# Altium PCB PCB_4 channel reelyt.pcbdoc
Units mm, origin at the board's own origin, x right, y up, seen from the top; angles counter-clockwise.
Board outline 128.64 x 103.34 mm, 2 copper layers (Top Layer, Bottom Layer); 44 components, 46 nets, 157 pads, 12 vias.
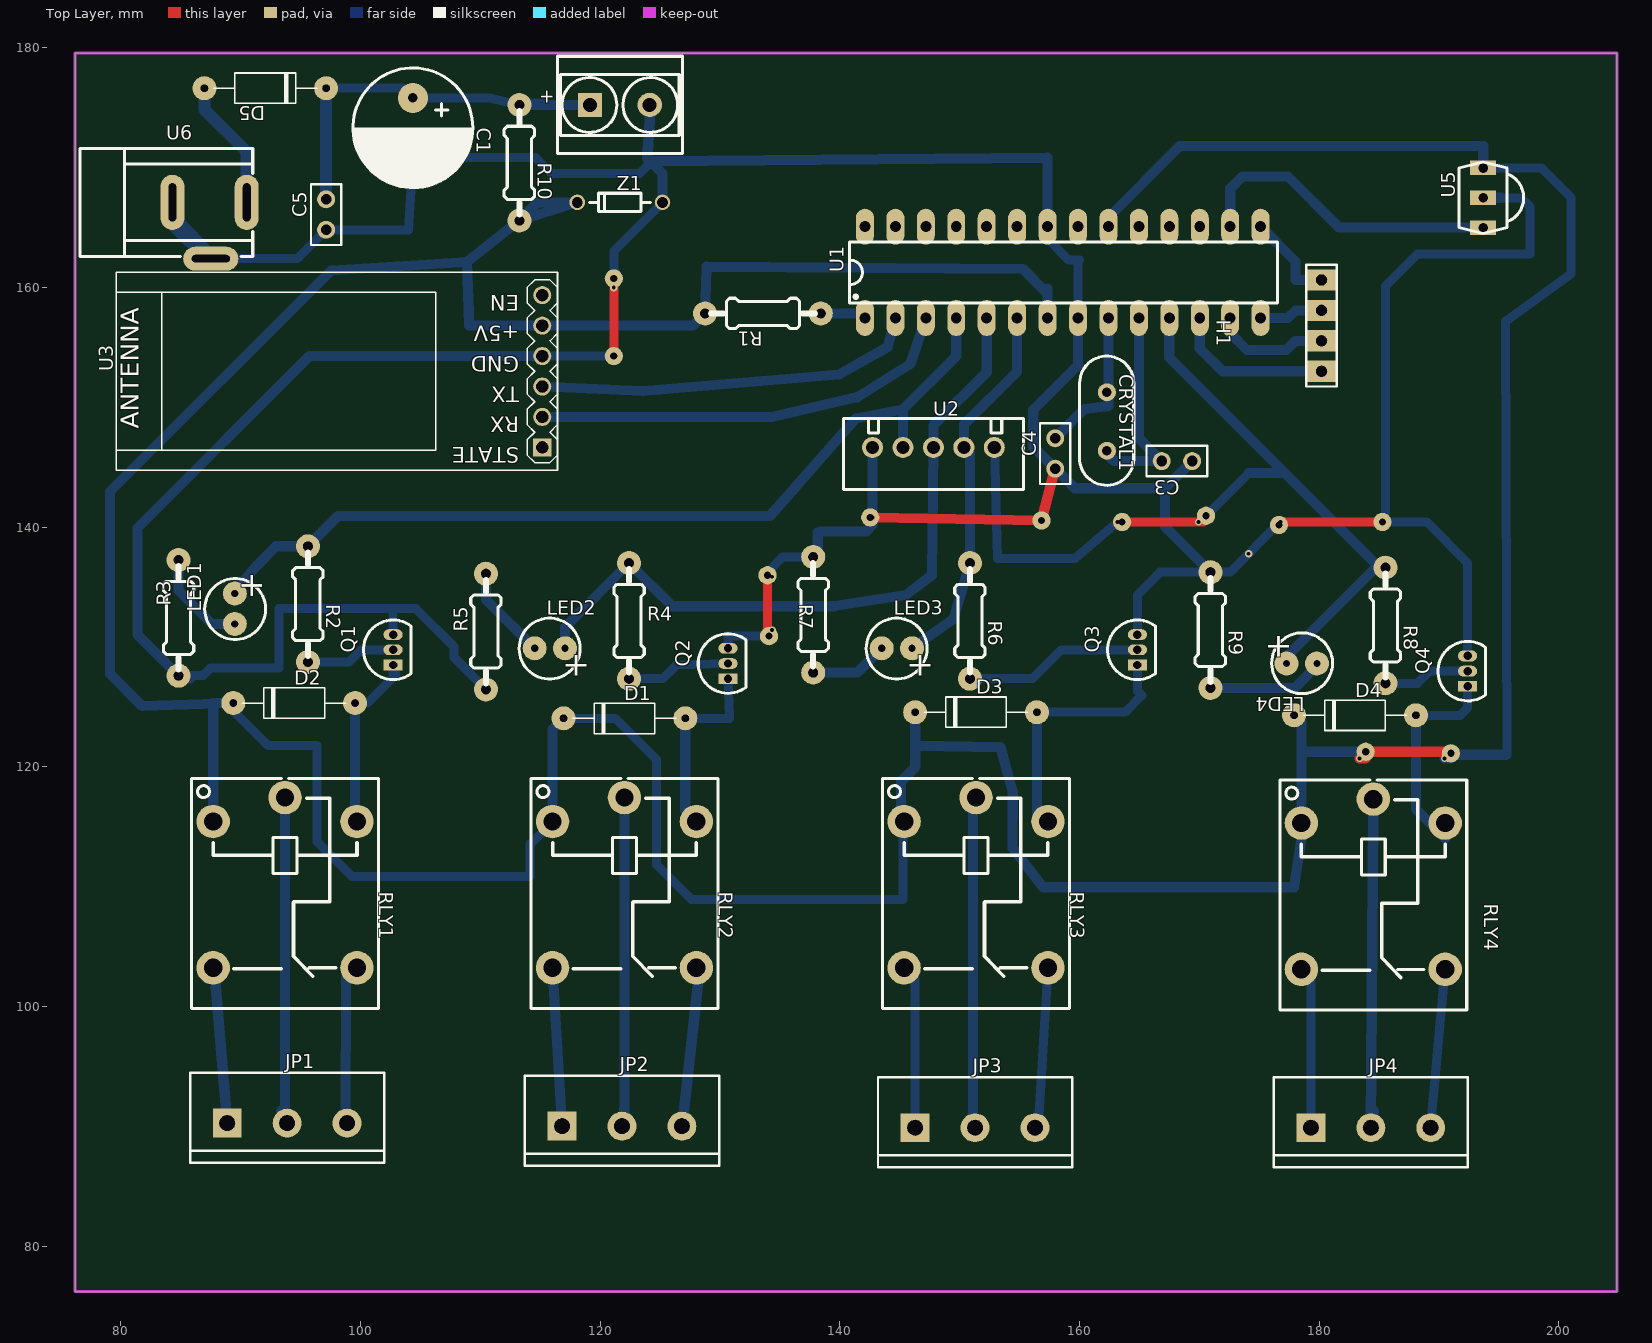
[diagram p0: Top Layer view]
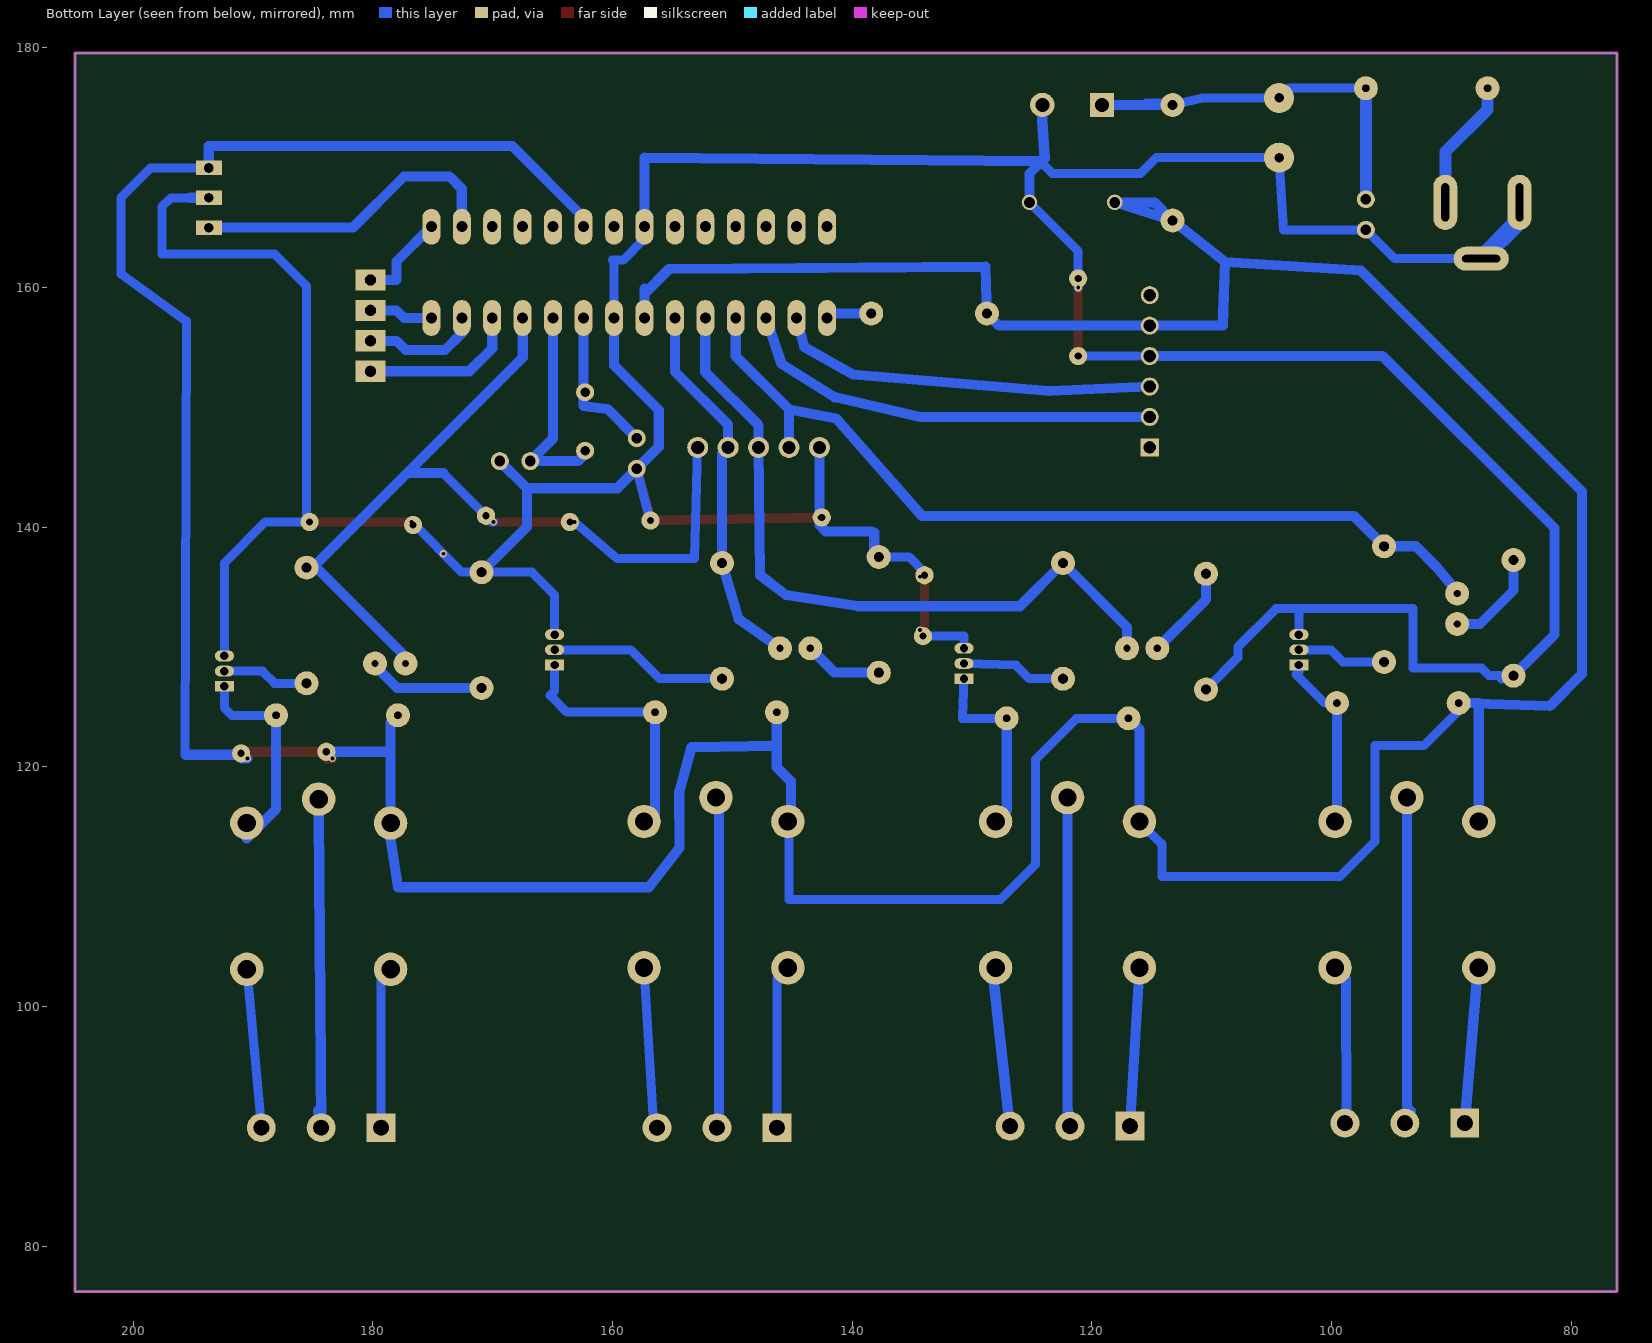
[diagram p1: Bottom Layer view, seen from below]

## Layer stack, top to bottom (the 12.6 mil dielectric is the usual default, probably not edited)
Top Layer: signal copper (thickness not stored)
Dielectric: dielectric 0.32, FR-4, Dk 4.8
Bottom Layer: signal copper (thickness not stored)

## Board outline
76.2,171.199 76.2,179.54 204.836,179.54 204.836,76.2 76.2,76.2

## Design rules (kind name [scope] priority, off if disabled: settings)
BoardOutlineClearance Default [All] p0: genericclearance=0.254 ignorepadtopadclearanceinfootprint=FALSE except(0: Region-CutoutEdge Arc-SplitContinuation Track-SplitContinuation SMDPad-SplitContinuation THPad-SplitContinuation Via-SplitContinuation Fill-SplitContinuation Poly-SplitContinuation Region-SplitContinuation Text-SplitContinuation; 0.5: Track-OutlineEdge SMDPad-OutlineEdge THPad-OutlineEdge Via-OutlineEdge Fill-OutlineEdge Region-OutlineEdge Poly-OutlineEdge Text-OutlineEdge Sheet-OutlineEdge Hole-OutlineEdge Track-CutoutEdge SMDPad-CutoutEdge THPad-CutoutEdge Via-CutoutEdge Fill-CutoutEdge Poly-CutoutEdge Text-CutoutEdge Sheet-CutoutEdge Hole-CutoutEdge)
Clearance Default [All] p1: gap=0.178 ignorepadtopadclearanceinfootprint=FALSE except(0: Region-Region; 0.5: Track-Track SMDPad-Track THPad-Track Via-Track Fill-Track Region-Track Poly-Track Text-Track Sheet-Track Hole-Track Track-SMDPad SMDPad-SMDPad THPad-SMDPad Via-SMDPad Fill-SMDPad Region-SMDPad Poly-SMDPad Text-SMDPad Sheet-SMDPad Hole-SMDPad Track-THPad SMDPad-THPad THPad-THPad Via-THPad Fill-THPad Region-THPad Poly-THPad Text-THPad Sheet-THPad Hole-THPad Track-Via SMDPad-Via THPad-Via Via-Via Fill-Via Region-Via Poly-Via Text-Via Sheet-Via Hole-Via Track-Fill SMDPad-Fill THPad-Fill Via-Fill Fill-Fill Region-Fill Poly-Fill Text-Fill Sheet-Fill Hole-Fill Track-Region SMDPad-Region THPad-Region Via-Region Fill-Region Poly-Region Text-Region Sheet-Region Hole-Region Track-Poly SMDPad-Poly THPad-Poly Via-Poly Fill-Poly Region-Poly Poly-Poly Text-Poly Sheet-Poly Hole-Poly Track-Text SMDPad-Text THPad-Text Via-Text Fill-Text Region-Text Poly-Text Text-Text Sheet-Text Hole-Text Track-Sheet SMDPad-Sheet THPad-Sheet Via-Sheet Fill-Sheet Region-Sheet Poly-Sheet Text-Sheet Sheet-Sheet Hole-Sheet Track-Hole SMDPad-Hole THPad-Hole Via-Hole Fill-Hole Region-Hole Poly-Hole Text-Hole Sheet-Hole Hole-Hole)
PasteMaskExpansion Common [All] p1: expansion=0
PlaneConnect Default [All] p1: planeconnectstyle=Relief reliefexpansion=0.508 reliefentries=4 reliefconductorwidth=0 reliefairgap=0.025
PolygonConnect Default [All] p1: connectstyle=Relief reliefentries=4 reliefconductorwidth=0 polygonreliefangle="90 Angle" airgapwidth=10
RoutingVias Default [All] p1: viastyle="Through Hole" holewidth=19.685 minholewidth=19.685 maxholewidth=2362 width=39.37 minwidth=39.37 maxwidth=3938
SolderMaskExpansion Common [All] p1: useseparateexpansions=TRUE expansion=2 expansionbottom=2
Width Default [All] p1: maxlimit=1000 minlimit=33 preferedwidth=33

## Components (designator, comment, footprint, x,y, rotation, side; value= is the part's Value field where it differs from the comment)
+ "5v in" H2-5.0-10.5X8.0MM 121.651,175.222 r90 top
C1 "1000uF" "CAP1000UFX25V-10X20(5MM, D-0.8)" 104.379,173.317 r270 top
C3 "22pf" CAP-TH_L5.0-W2.5-P2.54-D0.7 168.133,145.504 r180 top
C4 "22pf" CAP-TH_L5.0-W2.5-P2.54-D0.7 157.973,146.139 r90 top
C5 "22pf" CAP-TH_L5.0-W2.5-P2.54-D0.7 97.14,166.078 r90 top
CRYSTAL1 "mhz" CRYSTAL-TH_L10.8-W4.5-P4.88 162.291,148.806 r270 top
D1 "1N4007" 1N4007 122.032,124.041 r0 top
D2 "1N4007" 1N4007 94.473,125.311 r0 top
D3 "1N4007" 1N4007 151.369,124.549 r0 top
D4 "1N4007" 1N4007 182.992,124.295 r0 top
D5 "1N4007" 1N4007 92.06,176.619 r180 top
H1 "1X4 header" "HEADER - HEADER-FEMALE-2.54_1X4" 180.198,158.077 r270 top
JP1 "SCREWTERMINAL-5MM-3" SCREWTERMINAL-5MM-3 88.885,90.259 r0 top
JP2 "SCREWTERMINAL-5MM-3" SCREWTERMINAL-5MM-3 116.825,90.005 r0 top
JP3 "SCREWTERMINAL-5MM-3" SCREWTERMINAL-5MM-3 146.289,89.878 r0 top
JP4 "SCREWTERMINAL-5MM-3" SCREWTERMINAL-5MM-3 179.309,89.878 r0 top
LED1 "LED 5MM" LED-5MM-5MM 92.06,134.455 r90 top
LED2 "LED 5MM" LED-5MM-5MM 117.079,127.343 r0 top
LED3 "LED 5MM" LED-5MM-5MM 146.035,127.343 r0 top
LED4 "LED 5MM" LED-5MM-5MM 177.277,131.153 r180 top
Q1 "BC548B" TO-92-3_L4.9-W3.7-P1.27-L 102.728,129.756 r90 top
Q2 "BC548B" TO-92-3_L4.9-W3.7-P1.27-L 130.668,128.613 r90 top
Q3 "BC548B" TO-92-3_L4.9-W3.7-P1.27-L 164.831,129.756 r90 top
Q4 "BC548B" TO-92-3_L4.9-W3.7-P1.27-L 192.39,127.978 r90 top
R1 "10k" RESISTOR-1/4W 133.589,157.823 r180 top
R2 "100e" RESISTOR-1/4W 95.616,133.566 r270 top
R3 "220e" RESISTOR-1/4W 84.821,132.423 r90 top
R4 "100e" RESISTOR-1/4W 122.413,132.169 r270 top
R5 "220e" RESISTOR-1/4W 110.475,131.28 r90 top
R6 "100e" RESISTOR-1/4W 150.861,132.169 r270 top
R7 "220e" RESISTOR-1/4W 137.78,132.677 r270 top
R8 "100e" RESISTOR-1/4W 185.532,131.788 r270 top
R9 "220e" RESISTOR-1/4W 170.927,131.407 r270 top
R10 "10 e" RESISTOR-1/4W 113.269,170.396 r270 top
RLY1 "Реле пылесоса 12В" RELAY-TH_SRD-XXVDC-XL-C 93.711,110.325 r270 top
RLY2 "Реле пылесоса 12В" RELAY-TH_SRD-XXVDC-XL-C 122.032,110.325 r270 top
RLY3 "Реле пылесоса 12В" RELAY-TH_SRD-XXVDC-XL-C 151.369,110.325 r270 top
RLY4 "Реле пылесоса 12В" RELAY-TH_SRD-XXVDC-XL-C 184.516,110.198 r270 top
U1 "ATMEGA328 DIP" ATMEGA328P 158.608,161.252 r90 top
U2 "HEADER5" CONN-TH_HEADER5 147.813,146.647 r0 top
U3 "AMG AMGProductions GTIL HC-05 Bluetooth-module" WIRELESS-BLUETOOTH-HC-05 115.174,149.187 r90 top
U5 "TSOP1838" TSOP18XX 193.66,167.475 r90 top
U6 "BARREL JACK CONECTOR" "BARREL JACK_FOOTPRINT" 76.693,171.539 r0 top
Z1 "13Vz" DIODE-ZENER 121.651,167.094 r0 top

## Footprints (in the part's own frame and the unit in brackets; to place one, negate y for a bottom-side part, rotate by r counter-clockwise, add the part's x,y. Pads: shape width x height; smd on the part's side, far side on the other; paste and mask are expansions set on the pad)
1N4007 [mm]
  round 2 hole 0.61 slot 0.615 at 0 deg: A(5.08,0) K(-5.08,0)
  silkscreen extent -4.32,-1.27 4.32,1.27
ATMEGA328P [mm]
  oval 3x1.5 hole 0.914: 1(-3.81,16.51) 2(-3.81,13.97) 3(-3.81,11.43) 4(-3.81,8.89) 5(-3.81,6.35) 6(-3.81,3.81) 7(-3.81,1.27) 8(-3.81,-1.27) 9(-3.81,-3.81) 10(-3.81,-6.35) 11(-3.81,-8.89) 12(-3.81,-11.43) 13(-3.81,-13.97) 14(-3.81,-16.51) 15(3.81,-16.51) 16(3.81,-13.97) 17(3.81,-11.43) 18(3.81,-8.89) 19(3.81,-6.35) 20(3.81,-3.81) 21(3.81,-1.27) 22(3.81,1.27) 23(3.81,3.81) 24(3.81,6.35) 25(3.81,8.89) 26(3.81,11.43) 27(3.81,13.97) 28(3.81,16.51)
  silkscreen extent -2.54,-17.91 2.54,17.78
"BARREL JACK_FOOTPRINT" [mm]
  oval 2x4.6 hole 0.635 slot 3.175 at 90 deg: 1(13.82,-4.445) 2(7.62,-4.445)
  oval 4.6x2 hole 0.635 slot 3.175 at 0 deg: 3(10.82,-9.145)
  silkscreen extent -0.08,-8.94 14.32,0.06
"CAP1000UFX25V-10X20(5MM, D-0.8)" [mm]
  round 2.5 hole 0.8: 1(-2.492,0) 2(2.492,0)
  silkscreen extent -5,-5.1 5,5
CAP-TH_L5.0-W2.5-P2.54-D0.7 [mm]
  round 1.5 hole 0.9: 1(-1.27,0) 2(1.27,0)
  silkscreen extent -2.54,-1.27 2.54,1.27
CONN-TH_HEADER5 [mm]
  round 1.75 hole 1.1: 1(-5.08,0) 2(-2.54,0) 3(0,0) 4(2.54,0) 5(5.08,0)
  silkscreen extent -7.5,-3.5 7.5,2.4
CRYSTAL-TH_L10.8-W4.5-P4.88 [mm]
  round 1.5 hole 0.8: 1(-2.44,0) 2(2.44,0)
  silkscreen extent -5.46,-2.28 5.32,2.24
DIODE-ZENER [mil]
  round 51.2 hole 35.4: P$1(-140,0) P$2(140,0)
  silkscreen extent -100,-30 100,30
H2-5.0-10.5X8.0MM [mil]
  rect 80x80 hole 46: 1(0,98)
  round 80 hole 46: 2(0,-98)
  silkscreen extent -160,-205 160,205
"HEADER - HEADER-FEMALE-2.54_1X4" [mil]
  rect 70x98.42 hole 36 slot 36.2 at 90 deg: 1(-100,0) 2(0,0) 3(100,0) 4(200,0)
  silkscreen extent -150,-50 250,50
LED-5MM-5MM [mm]
  round 2 hole 0.6: 1(-2.54,2.54) 2(0,2.54)
  silkscreen extent -3.83,-0.02 1.24,5.06
RELAY-TH_SRD-XXVDC-XL-C [mil]
  round 110 hole 60: 1(-200.79,-236.22) 2(279.53,-236.2) 3(279.53,236.2) 4(-200.79,236.22) 5(-279.53,0)
  silkscreen extent -342,-307 413,307
RESISTOR-1/4W [mm]
  round 2 hole 0.8 slot 0.805 at 0 deg: 1(-4.826,0) 2(4.826,0)
  silkscreen extent -4.32,-1.27 4.32,1.27
SCREWTERMINAL-5MM-3 [mil]
  rect 95x95 hole 51.18 slot 51.38 at 0 deg: 1(0,0)
  round 95 hole 51.18 slot 51.38 at 0 deg: 2(196.85,0) 3(393.7,0)
  silkscreen extent -122,-130 516,165
TO-92-3_L4.9-W3.7-P1.27-L [mm]
  rect 0.9x1.6 hole 0.7: 1(-1.27,0)
  oval 0.9x1.6 hole 0.7: 2(0,0) 3(1.27,0)
  silkscreen extent -2.48,-1.5 2.48,2.48
TSOP18XX [mil]
  rect 47.7x85.9 hole 32: GND(0,-1.05) OUT(-98,-1.05) VCC(98,-1.05)
  silkscreen extent -118,-134 118,78
WIRELESS-BLUETOOTH-HC-05 [mm]
  rect 1.508x1.508 hole 1: 1(-2.54,0)
  round 1.508 hole 1: 2(0,0) 3(2.54,0) 4(5.08,0) 5(7.62,0) 6(10.16,0)
  silkscreen extent -4.45,-1.27 12.06,35.56

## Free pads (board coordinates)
  round 1.524 hole 0.6: 7(176.642,140.17) 9(163.561,140.424) 12(142.542,140.805) 13(156.83,140.551) 14(185.278,140.424) 15(183.881,121.247) 16(190.993,121.12) 17(170.56,140.946) 18(121.143,160.744) 21(121.143,154.267) 24(133.97,135.979) 25(134.097,130.899)

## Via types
v1: diameter 0.62, hole 0.31, Top Layer to Bottom Layer, 12 vias

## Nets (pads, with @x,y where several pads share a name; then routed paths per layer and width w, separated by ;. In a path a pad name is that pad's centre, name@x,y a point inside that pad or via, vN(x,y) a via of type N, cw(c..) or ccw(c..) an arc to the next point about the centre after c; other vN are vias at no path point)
1: LED1.2 R2.1 U1.4 U2.2 | length 78.5
  Bottom Layer w0.85: LED1.2@89.393,134.455 91.298,136.741 92.949,138.392 R2.1@95.87,138.392 ; R2.1 98.156,140.932 134.173,140.932 141.336,149.06 145.273,149.822 ; U1.4 149.718,154.267 145.273,149.822 ; 145.273,149.822 145.273,146.698 U2.2 145.273,149.822
2: LED2.2 R4.1 U1.5 U2.3 | length 60
  Bottom Layer w0.85: LED2.2 117.079,131.661 R4.1 126.012,133.396 139.515,133.396 145.527,134.328 147.686,135.979 U2.3 147.813,148.483 152.258,152.928 U1.5
3: LED3.2 R6.1 U1.6 U2.4 | length 31.6
  Bottom Layer w0.85: LED3.2 149.464,132.296 R6.1 150.861,146.139 U2.4 150.353,148.539 154.798,152.984 U1.6
4: LED4.2 pad.17 R8.1 U1.11 U2.5 | length 76.3
  Top Layer w0.75: v1(163.18,140.424) pad.17@170.292,140.424
  Bottom Layer w0.75: U2.5 153.147,137.376 159.624,137.376 v1(163.18,140.424) ; v1(169.931,140.424) 170.038,140.424 pad.17 174.122,144.508
  Bottom Layer w0.85: U1.11 167.498,154.15 R8.1@184.869,136.779 ; 174.122,144.508 177.139,144.508 ; LED4.2 177.277,129.188 184.868,136.779 185.033,136.614 R8.1
+5V: C1.1 D5.K | length 16.5
  Bottom Layer w0.75: D5.K 103.569,176.619 C1.1 110.777,175.809 113.269,175.222
CRYSTAL1_1: C4.2 CRYSTAL1.1 U1.9 | length 12.6
  Bottom Layer w0.85: C4.2 160.413,149.847 162.164,150.076 ; 162.418,150.101 U1.9
CRYSTAL1_2: C3.2 CRYSTAL1.2 U1.10 | length 17.9
  Bottom Layer w0.85: CRYSTAL1.2@162.037,146.366 162.899,145.504 C3.2 164.958,147.409 U1.10
GND: +.2 C1.2 C3.1 C4.1 C5.1 pad.12 pad.13 pad.14 pad.18 pad.21 pad.24 pad.25 Q1.3 Q2.3 Q3.3 Q4.3 R3.1 R5.1 R7.1 R9.1 U1.8 U1.22 U2.1 U3.4 U5.GND U6.2 U6.3 Z1.P$2 | length 395.1
  Top Layer w0.75: v1(121.143,154.267) v1(121.143,159.982) ; pad.24 133.97,131.026 pad.25 ; v1(176.769,140.424) v1(185.278,140.424) pad.14@185.278,140.678
  Top Layer w0.85: pad.12 pad.13 C4.1
  Bottom Layer w0.75: R3.1 86.853,127.597 87.488,128.232 93.203,128.232 93.203,133.185 102.601,133.185 102.728,133.058 ; U6.3 94.725,162.394 C5.1 103.998,164.808 C1.2 114.617,170.825 115.936,169.507 123.302,169.507 124.318,170.523 ; Q1.3@102.728,131.084 102.728,133.058 ; R5.1 107.808,129.121 107.808,130.01 104.633,133.185 102.728,133.185 102.728,133.058 ; U3.4 v1(121.143,154.267) ; v1(121.143,159.982) 121.143,163.03 Z1.P$2 ; Q2.3@130.668,129.941 130.668,130.899 pad.25 ; pad.24 133.97,136.233 135.24,137.503 R7.1 ; U1.22 157.338,164.046 159.116,162.268 160.005,162.268 159.878,162.141 U1.8 ; C4.1 157.338,142.329 pad.13 ; Q3.3@164.831,131.084 164.831,134.328 166.736,136.233 R9.1 172.578,136.233 v1(176.769,140.424) ; Q4.3@192.39,129.306 192.39,136.995 188.961,140.424 v1(185.278,140.424) 185.532,140.678 185.532,160.109 188.199,162.776 197.597,162.776 197.597,166.713 196.835,167.475 U5.GND ; pad.13 157.211,140.424 pad.13
  Bottom Layer w0.85: R3.1@85.708,127.472 R3.1@85.583,127.597 ; R3.1@85.772,127.407 R3.1@85.583,127.597 ; 85.805,127.375 R3.1@85.583,127.597 ; U3.4 95.743,154.267 81.392,139.916 81.392,131.026 R3.1 ; +.2 124.14,173.901 123.937,170.777 ; Z1.P$2 125.207,169.507 123.937,170.777 ; R7.1 138.362,137.503 R7.1@138.415,137.556 ; R7.1@138.161,137.45 138.161,139.535 ; 138.415,139.642 142.204,139.642 142.733,140.17 U2.1 ; U1.22 157.338,170.821 124.318,170.523 ; U1.8 159.878,153.499 156.145,149.766 156.145,146.697 C4.1 159.604,143.237 167.136,143.237 ; C3.1 167.136,143.237 ; R9.1 169.979,137.181 169.032,138.128 167.136,140.023 167.136,143.237 ; U5.GND@193.686,167.475 195.197,167.475 ; R3.1 R3.1@85.583,127.597 ; R3.1 R3.1@85.583,127.597 ; R3.1 R3.1@85.583,127.597 ; 123.937,170.777 124.318,170.523 ; 123.937,170.777 124.318,170.523
  Bottom Layer w1.5: U6.2 84.313,165.593 U6.3@87.513,162.394
  other v1: 134.351,131.407 134.351,135.852 174.11,137.766 142.733,140.805
IR: U1.16 U5.OUT | length 26.5
  Bottom Layer w0.85: U1.16 172.578,168.237 173.594,169.253 177.404,169.253 181.671,164.986 U5.OUT
LED2_1: LED2.1 R5.2 | length 7.9
  Bottom Layer w0.85: R5.2 110.475,133.947 LED2.1
LED3_1: LED3.1 R7.2 | length 6.6
  Bottom Layer w0.85: R7.2 141.463,127.851 LED3.1
LED4_1: LED4.1 R9.2 | length 9.8
  Bottom Layer w0.85: R9.2 177.978,126.581 179.817,128.42 LED4.1
Q1_1: D2.A Q1.1 RLY1.4 | length 15.3
  Bottom Layer w0.75: D2.A 100.569,125.311 102.982,127.724 102.855,127.724 102.728,127.851 Q1.1@102.728,128.428
  Bottom Layer w0.85: D2.A 99.553,115.583 RLY1.4
Q2_2: Q2.2 R4.2 | length 8.7
  Bottom Layer w0.75: R4.2 125.207,127.343 126.35,128.486 Q2.2
Q3_2: Q3.2 R6.2 | length 15
  Bottom Layer w0.75: R6.2 156.068,127.343 158.481,129.756 Q3.2
Q4_2: Q4.2 R8.2 | length 7.3
  Bottom Layer w0.75: R8.2 188.199,126.962 189.215,127.978 Q4.2
R1_1: R1.1 U1.1 | length 3.8
  Bottom Layer w0.85: R1.1 141.717,157.823 U1.1
R2_2: Q1.2 R2.2 | length 7.5
  Bottom Layer w0.75: R2.2 99.045,128.74 100.061,129.756 Q1.2
R3_2: LED1.1 R3.2 | length 8
  Bottom Layer w0.85: R3.2 84.821,134.709 87.615,131.915 LED1.1@89.139,131.915
R10_1: +.1 R10.1 | length 10.9
  Bottom Layer w0.85: R10.1 +.1 ; R10.1@112.895,175.349 115.421,175.349 R10.1@112.895,175.349
RLY1_2: RLY1.2 | length 13.7
  Bottom Layer w0.85: RLY1.2 87.808,103.129 88.885,90.259 88.885,90.894
RLY1_3: RLY1.3 | length 13.5
  Bottom Layer w0.85: 98.758,90.132 98.791,102.306 RLY1.3
RLY1_5: RLY1.5 | length 27.5
  Bottom Layer w0.85: RLY1.5 93.711,91.585 93.393,91.268 93.758,90.132
RLY2_4: D1.A Q2.1 RLY2.4 | length 16
  Bottom Layer w0.75: D1.A 130.795,124.041 130.795,124.168 Q2.1
  Bottom Layer w0.85: D1.A 127.112,116.345 RLY2.4
RLY3_4: D3.A Q3.1 RLY3.4 | length 21.4
  Bottom Layer w0.75: D3.A 163.815,124.549 165.212,125.946 164.831,126.327 Q3.1@164.831,128.428
  Bottom Layer w0.85: D3.A@156.449,124.548 156.449,124.546 156.449,124.544 156.449,124.538 156.449,124.527 156.449,124.506 156.449,124.463 156.449,124.376 156.449,124.203 156.449,123.857 156.449,123.165 156.449,121.782 156.449,116.091 RLY3.4@157.115,115.425
RLY4_4: D4.A Q4.1 RLY4.4 | length 17.6
  Bottom Layer w0.75: D4.A 191.755,124.295 192.39,124.93 Q4.1@192.39,126.649
  Bottom Layer w0.85: D4.A@188.072,124.293 188.072,124.291 188.072,124.288 188.072,124.28 188.072,124.265 188.072,124.235 188.072,124.176 188.072,124.057 188.072,123.819 188.072,123.342 188.072,122.39 188.072,116.472 RLY4.4@190.516,114.028
RX: U1.3 U3.2 | length 35.7
  Bottom Layer w0.85: U3.2 124.318,149.187 134.351,149.187 141.463,150.838 145.908,153.632 U1.3
S$38057: pad.7
S$38160: pad.9
TX: U1.2 U3.3 | length 32
  Bottom Layer w0.85: U3.3 123.556,151.346 139.939,152.743 144.003,155.029 U1.2
U1_9: C5.2 | length 9.3
  Bottom Layer w1: C5.2 97.14,172.936 97.14,176.619
U1_12: H1.4 U1.12 | length 13.5
  Bottom Layer w0.85: U1.12 170.038,154.902 171.943,152.997 H1.4
U1_13: H1.3 U1.13 | length 9.8
  Bottom Layer w0.85: U1.13 172.578,156.172 173.975,154.775 177.262,154.775 178.024,155.537 ; 178.022,155.537 H1.3
U1_14: H1.2 U1.14 | length 5.3
  Bottom Layer w0.85: U1.14 177.387,157.442 178.022,158.077 H1.2
U1_15: H1.1 U1.15 | length 7.8
  Bottom Layer w0.85: U1.15 178.022,162.157 178.022,160.617 H1.1
U3_1: D5.A U6.1 | length 11
  Bottom Layer w1: D5.A 86.98,174.841 90.513,171.308 U6.1
VCC: D1.K D2.K D3.K D4.K pad.15 pad.16 R1.2 R10.2 RLY1.1 RLY2.1 RLY3.1 RLY4.1 U1.7 U1.20 U3.5 U5.VCC Z1.P$1 | length 433.8
  Top Layer w0.85: v1(183.373,120.687) pad.15@183.855,120.687 ; pad.15 pad.16@191.146,121.247
  Bottom Layer w0.75: D2.K 89.393,124.676 92.314,121.755 96.378,121.755 96.378,113.754 99.299,110.833 114.158,110.833 114.158,113.551 RLY2.1 ; D1.K 121.27,124.041 124.699,120.612 124.699,111.849 127.62,108.928 145.273,108.928 145.273,115.267 RLY3.1@145.115,115.425 ; U5.VCC 198.537,169.964 201.026,167.475 201.026,161.125 195.565,157.188 195.692,120.993
  Bottom Layer w0.85: RLY1.1 87.711,125.311 D2.K 81.803,125.057 79.106,127.754 79.106,142.964 97.541,161.399 108.887,162.128 ; RLY2.1 116.032,122.653 116.032,123.121 D1.K ; R1.2@128.763,157.399 128.89,161.717 155.263,161.547 157.338,159.474 ; R1.2 127.747,156.807 U3.5 109.078,156.807 108.887,162.128 ; RLY3.1@145.115,115.425 145.115,118.797 145.496,119.178 146.289,119.971 D3.K ; 146.289,119.972 146.289,121.755 153.401,121.628 154.435,117.907 154.417,113.246 156.957,109.944 177.912,109.944 178.516,114.028 178.516,123.691 D4.K ; U1.7 157.338,159.898 ; U1.20 162.418,165.837 168.374,171.793 193.685,171.793 U5.VCC ; 178.547,121.247 pad.15@183.404,121.247 ; v1(190.459,120.687) pad.16@190.967,120.687 ; pad.16@190.993,120.993 195.591,120.993 ; 108.887,162.128 R10.2 ; 108.887,162.128 R10.2 ; R10.2 114.793,167.094 Z1.P$1 R10.2
X2_1: RLY2.3 | length 13.3
  Bottom Layer w0.85: 126.858,90.005 RLY2.3@128.318,103.226
X2_2: RLY2.5 | length 29.9
  Bottom Layer w0.85: 121.825,90.005 122.032,91.712 RLY2.5 ; 122.032,89.751 122.032,92.241
X2_3: RLY2.2 | length 13.2
  Bottom Layer w0.85: RLY2.2 116.825,90.005
X3_1: RLY3.3 | length 13
  Bottom Layer w0.75: 156.576,90.251 RLY3.3
X3_2: RLY3.5 | length 27.6
  Bottom Layer w0.85: RLY3.5@151.115,117.424 151.115,90.851 151.289,89.878
X3_3: RLY3.2 | length 13.7
  Bottom Layer w0.75: RLY3.2 146.289,102.305 146.289,89.878
X4_1: RLY4.3 | length 13.3
  Bottom Layer w0.75: 189.309,89.878 RLY4.3
X4_2: RLY4.5 | length 27.7
  Bottom Layer w0.85: 184.516,91.331 184.579,91.268 184.309,89.878 RLY4.5@184.516,116.028
X4_3: RLY4.2 | length 13.5
  Bottom Layer w0.75: RLY4.2 179.309,102.305 179.309,89.878
pads on no net: JP1.1 JP1.2 JP1.3 JP2.1 JP2.2 JP2.3 JP3.1 JP3.2 JP3.3 JP4.1 JP4.2 JP4.3 U1.17 U1.18 U1.19 U1.21 U1.23 U1.24 U1.25 U1.26 U1.27 U1.28 U3.1 U3.6

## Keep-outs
Board Outline Layer:
  the board outline again, w0.254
